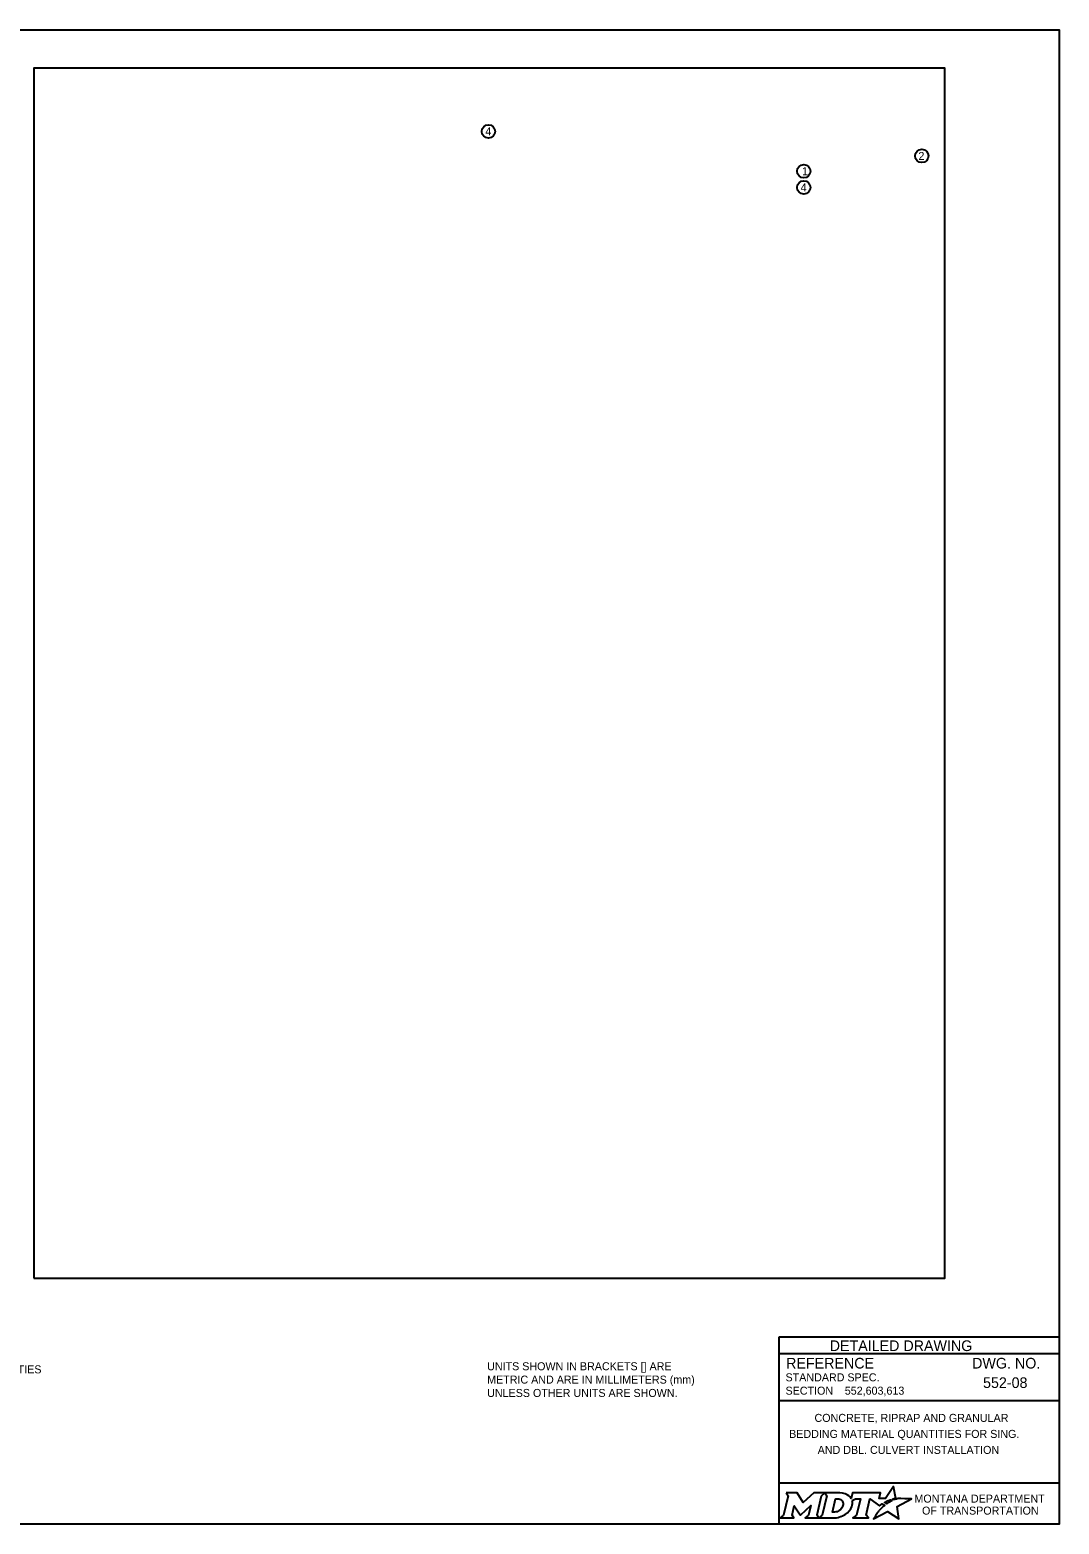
# Model space of a CAD drawing. Extents: x 49991.4 to 50021, y 49987.6 to 50011.4.
# Drawn here: x 50009.04 to 50016.75, y 49987.8 to 49999 of the extents above; entities that cross this region are included whole.
import ezdxf

# ---------------------------------------------------------------- set-up
doc = ezdxf.new("R2010")
doc.units = 0
for name, color, linetype in [('Default', 7, 'Continuous'), ('Level 1', 7, 'Continuous'), ('Level 2', 7, 'Continuous'), ('Level 5', 7, 'Continuous')]:
    doc.layers.add(name, color=color, linetype=linetype)

msp = doc.modelspace()

# ---------------------------------------------------------------- linework, layer by layer
at = {"layer": 'Default'}
for points in [[(50015.513, 49987.981), (50015.502, 49987.987), (50015.514, 49987.99), (50015.526, 49987.991), (50015.508, 49988.082), (50015.449, 49987.99), (50015.401, 49987.99), (50015.412, 49988.034), (50015.202, 49988.034), (50015.192, 49987.991), (50015.186, 49988)], [(50014.706, 49988.034), (50014.72, 49988.01), (50014.686, 49987.867), (50014.66, 49987.845), (50014.762, 49987.845), (50014.749, 49987.867), (50014.765, 49987.937), (50014.809, 49987.868), (50014.814, 49987.868), (50014.889, 49987.938), (50014.872, 49987.867), (50014.848, 49987.845), (50014.949, 49987.845), (50014.936, 49987.868), (50014.969, 49988.011)], [(50014.969, 49988.011), (50014.994, 49988.034), (50014.912, 49988.034), (50014.832, 49987.961), (50014.788, 49988.034), (50014.706, 49988.034)], [(50015.108, 49988.034), (50014.994, 49988.034), (50015.009, 49988.011), (50014.975, 49987.867), (50014.949, 49987.845), (50015.06, 49987.845)], [(50015.132, 49987.947), (50015.13, 49987.939), (50015.127, 49987.93), (50015.123, 49987.922), (50015.118, 49987.914), (50015.111, 49987.907), (50015.103, 49987.901), (50015.095, 49987.896), (50015.086, 49987.892), (50015.077, 49987.89), (50015.067, 49987.889), (50015.052, 49987.889), (50015.075, 49987.989), (50015.091, 49987.989), (50015.099, 49987.988), (50015.106, 49987.986), (50015.113, 49987.983), (50015.119, 49987.979), (50015.124, 49987.974), (50015.128, 49987.968), (50015.13, 49987.962), (50015.132, 49987.955), (50015.132, 49987.952), (50015.132, 49987.947)], [(50015.199, 49987.975), (50015.224, 49987.988), (50015.261, 49987.988), (50015.232, 49987.867), (50015.205, 49987.845), (50015.321, 49987.845), (50015.304, 49987.867), (50015.332, 49987.988), (50015.403, 49987.936), (50015.424, 49987.951), (50015.444, 49987.94)], [(50015.388, 49987.884), (50015.373, 49987.86), (50015.368, 49987.852), (50015.362, 49987.844), (50015.36, 49987.839), (50015.465, 49987.893), (50015.549, 49987.838), (50015.536, 49987.93), (50015.643, 49987.989), (50015.594, 49987.989), (50015.564, 49987.99), (50015.543, 49987.99), (50015.536, 49987.989), (50015.531, 49987.987), (50015.523, 49987.985), (50015.513, 49987.981)], [(50015.462, 49987.954), (50015.46, 49987.952), (50015.442, 49987.961), (50015.452, 49987.967), (50015.456, 49987.969), (50015.465, 49987.973), (50015.47, 49987.976), (50015.478, 49987.979), (50015.485, 49987.982), (50015.497, 49987.974), (50015.493, 49987.972), (50015.489, 49987.97), (50015.484, 49987.967), (50015.479, 49987.965), (50015.478, 49987.963), (50015.475, 49987.962), (50015.472, 49987.96), (50015.47, 49987.959), (50015.467, 49987.957), (50015.465, 49987.955), (50015.462, 49987.954)], [(50015.106, 49987.852), (50015.114, 49987.855), (50015.127, 49987.86), (50015.148, 49987.871)], [(50015.402, 49987.9), (50015.402, 49987.9)]]:
    msp.add_lwpolyline(points, dxfattribs=at)
for centre in [(50012.474, 49998.238), (50014.837, 49997.818)]:
    msp.add_circle(centre, 0.05, dxfattribs=at)
for centre, radius, start, end in [((50015.131, 49987.955), 0.0709, 339.5329, 15.8582), ((50015.087, 49987.973), 0.118, 300.9103, 339.1383)]:
    msp.add_arc(centre, radius, start, end, dxfattribs=at)
for centre, major_axis, ratio, start_param, end_param in [((50015.106, 49987.986), (0.0834, -0.0037), 0.568097, 0.61298, 1.570796), ((50015.161, 49987.994), (0.0361, -0.0295), 0.469099, 1.225588, 1.570796), ((50015.06, 49987.993), (0, 0.148), 0.987302, 3.139398, 3.456847), ((50015.395, 49987.892), (-0.00694, -0.00806), 0.008222, 0, 3.137361), ((50015.412, 49987.911), (-0.0098, -0.0102), 0.016458, 3.141593, 6.279097), ((50015.433, 49987.93), (-0.0112, -0.0097), 0.021651, 3.157348, 6.283185)]:
    msp.add_ellipse(centre, major_axis=major_axis, ratio=ratio, start_param=start_param, end_param=end_param, dxfattribs=at)
at = {"layer": 'Level 1'}
msp.add_lwpolyline([(49999.384, 49998.999), (50016.75, 49998.999), (50016.75, 49987.799), (49999.384, 49987.799)], close=True, dxfattribs=at)
at = {"layer": 'Level 2'}
msp.add_lwpolyline([(50009.067, 49989.642), (50015.893, 49989.642), (50015.893, 49998.712), (50009.067, 49998.712)], close=True, dxfattribs=at)
for centre in [(50015.721, 49998.054), (50014.837, 49997.94)]:
    msp.add_circle(centre, 0.05, dxfattribs=at)
at = {"layer": 'Level 5'}
for p, q in [((50016.75, 49989.199), (50014.65, 49989.199)), ((50014.65, 49989.199), (50014.65, 49987.799)), ((50016.75, 49989.074), (50014.65, 49989.074)), ((50016.386, 49988.859), (50016.386, 49988.859)), ((50015.144, 49988.799), (50015.144, 49988.799)), ((50016.75, 49988.724), (50014.65, 49988.724)), ((50015.7, 49988.475), (50015.7, 49988.475)), ((50016.75, 49988.106), (50014.65, 49988.106))]:
    msp.add_line(p, q, dxfattribs=at)

# ---------------------------------------------------------------- texts
at = {"layer": 'Default'}
for s, p in [('4', (50012.45, 49998.208)), ('4', (50014.813, 49997.788)), ('MONTANA DEPARTMENT', (50015.666, 49987.96)), ('OF TRANSPORTATION', (50015.723, 49987.87))]:
    msp.add_text(s, height=0.06, dxfattribs=at).set_placement(p)
at = {"layer": 'Level 2'}
for s, height, p in [('2', 0.06, (50015.696, 49998.024)), ('1', 0.06, (50014.824, 49997.91)), ('FOR PIPES WITH SKEW BEVEL ENDS - DIVIDE THE QUANTITIES', 0.06, (50006.659, 49988.929)), ('UNITS SHOWN IN BRACKETS [] ARE ', 0.06, (50012.464, 49988.952)), ('METRIC AND ARE IN MILLIMETERS (mm) ', 0.06, (50012.464, 49988.852)), ('552-08', 0.08, (50016.18, 49988.819)), ('UNLESS OTHER UNITS ARE SHOWN.', 0.06, (50012.464, 49988.752)), ('552,603,613', 0.06, (50015.144, 49988.769)), ('CONCRETE, RIPRAP AND GRANULAR ', 0.06, (50014.917, 49988.565)), ('BEDDING MATERIAL QUANTITIES FOR SING.', 0.06, (50014.727, 49988.445)), ('AND DBL. CULVERT INSTALLATION', 0.06, (50014.941, 49988.325))]:
    msp.add_text(s, height=height, dxfattribs=at).set_placement(p)
at = {"layer": 'Level 5'}
for s, height, p in [('DETAILED DRAWING', 0.0799, (50015.031, 49989.096)), ('REFERENCE', 0.08, (50014.704, 49988.965)), ('DWG. NO.', 0.08, (50016.098, 49988.965)), ('STANDARD SPEC.', 0.06, (50014.7, 49988.869)), ('SECTION', 0.06, (50014.7, 49988.769))]:
    msp.add_text(s, height=height, dxfattribs=at).set_placement(p)

doc.saveas('drawing.dxf')
